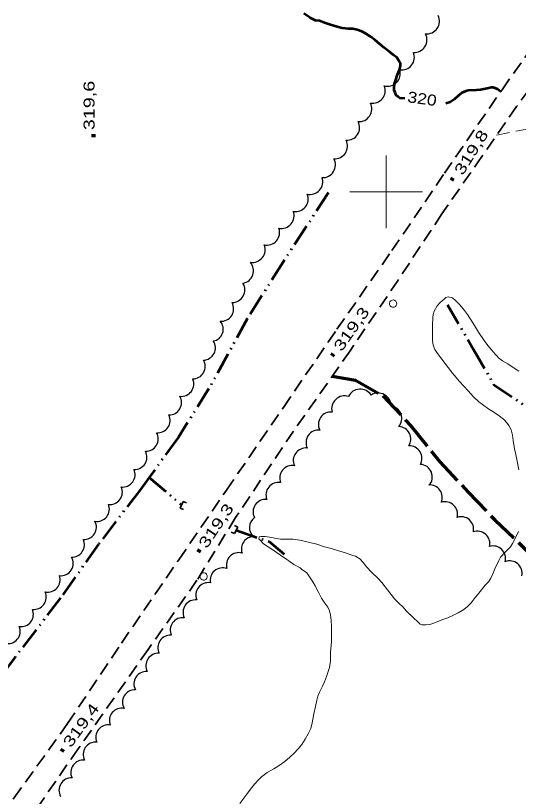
# Model space of a CAD drawing. Extents: x 240591 to 242335, y 5323482 to 5326937.
# Drawn here: x 241498.3 to 241636.3, y 5325234.2 to 5325448.3 of the extents above; entities that cross this region are included whole.
import ezdxf

# ---------------------------------------------------------------- set-up
doc = ezdxf.new("R2010")
doc.units = 0
doc.header["$LTSCALE"] = 1.2
for name, pattern in [('DASH_DOUBLE_DOT', [9.2, 5, -1.2, 0.3, -1.2, 0.3, -1.2]), ('LONG_DASHED', [7.5, 6, -1.5]), ('MEDIUM_DASHED', [4.5, 3, -1.5])]:
    doc.linetypes.add(name, pattern=pattern)
for name, color, linetype, lineweight in [('1', 7, 'Continuous', 53), ('19', 7, 'Continuous', 13), ('2', 7, 'Continuous', 13), ('21', 7, 'Continuous', 53), ('22', 7, 'LONG_DASHED', 70), ('26', 7, 'Continuous', 35), ('3', 7, 'Continuous', 140), ('36', 7, 'Continuous', 13), ('4', 7, 'DASH_DOUBLE_DOT', 53), ('44', 7, 'Continuous', 25), ('61', 7, 'Continuous', 13)]:
    doc.layers.add(name, color=color, linetype=linetype, lineweight=lineweight)

msp = doc.modelspace()

# ---------------------------------------------------------------- linework, layer by layer
at = {"layer": '1'}
for points in [[(241605.1, 5325425.6), (241603.8, 5325425.7), (241603.3, 5325426), (241602.8, 5325426.5), (241602.5, 5325427.2), (241602.2, 5325427.9), (241602.2, 5325428.5), (241602.3, 5325429.7), (241602.6, 5325430.4), (241603.1, 5325432.2), (241603.7, 5325433.4), (241603.9, 5325434.5), (241603.9, 5325435.3), (241603.6, 5325435.8), (241602.9, 5325436.8), (241601.9, 5325437.6), (241600.9, 5325438.4), (241599.4, 5325439.6), (241597, 5325441.6), (241595.8, 5325442.5), (241594.5, 5325443.3), (241593.3, 5325444), (241592.1, 5325444.4), (241590.9, 5325444.7), (241589.7, 5325444.7), (241587.9, 5325444.9), (241586.6, 5325445.2), (241584.7, 5325445.8), (241583.4, 5325446.2), (241581.7, 5325446.9), (241580.6, 5325447), (241579.5, 5325447.5), (241579.1, 5325447.8), (241577.4, 5325448.9)], [(241631.4, 5325427.5), (241630.6, 5325428.1), (241629.5, 5325428.6), (241628.8, 5325428.6), (241628.2, 5325428.4), (241625.9, 5325428), (241624.8, 5325427.9), (241622.5, 5325427.8), (241621.9, 5325427.6), (241620.8, 5325427.1), (241619.8, 5325426.3), (241618.7, 5325425.3), (241617.6, 5325424.6), (241616.4, 5325424.2)]]:
    msp.add_lwpolyline(points, dxfattribs=at)
at = {"layer": '19', "linetype": 'MEDIUM_DASHED'}
msp.add_lwpolyline([(241630.3, 5325415.5), (241640.5, 5325417.6), (241648.5, 5325417.1), (241657.7, 5325414.1), (241658.9, 5325416.3)], dxfattribs=at)
at = {"layer": '2'}
for points in [[(241636.4, 5325350.8), (241634.9, 5325351.8), (241633.4, 5325352.8), (241631.9, 5325353.7), (241630.8, 5325354.5), (241630.5, 5325354.9), (241629.9, 5325355.5), (241629, 5325356.6), (241627.9, 5325357.9), (241626.9, 5325359.2), (241625.3, 5325361.5), (241624.5, 5325362.9), (241623.8, 5325364.1), (241622.3, 5325366.4), (241621.5, 5325367.5), (241620.2, 5325369), (241619, 5325370.2), (241618.2, 5325370.9), (241617, 5325371.2), (241616.4, 5325371), (241615.9, 5325370.6), (241614.8, 5325369.7), (241614, 5325368.7), (241613.2, 5325367.3), (241612.9, 5325366.4), (241612.8, 5325365.5), (241612.7, 5325363.5), (241612.7, 5325361.7), (241612.7, 5325359.2), (241612.9, 5325358), (241613.4, 5325356.8), (241614.1, 5325355.7), (241615.3, 5325354.1), (241617, 5325351.8), (241618.2, 5325350.3), (241620.1, 5325348), (241621.3, 5325346.7), (241622.5, 5325345.4), (241624, 5325343.8), (241625.4, 5325342.4), (241626.4, 5325341.7), (241628.2, 5325340.4), (241629.3, 5325339.8), (241631, 5325338.6), (241632.2, 5325337.7), (241633.3, 5325336.5), (241633.7, 5325335.9), (241634.3, 5325334.7), (241634.7, 5325333.3), (241634.9, 5325331.8), (241635.2, 5325329.5), (241635.6, 5325328), (241635.9, 5325326.6), (241636.4, 5325323.8)], [(241636.3, 5325306.9), (241635.6, 5325305.3), (241634.7, 5325303.6), (241634.1, 5325302.7), (241633.4, 5325301.9), (241632.7, 5325301.2), (241631.4, 5325299.8), (241630.9, 5325298.9)]]:
    msp.add_lwpolyline(points, dxfattribs=at)
at = {"layer": '2', "linetype": 'LONG_DASHED'}
for points in [[(241630.9, 5325298.9), (241629.8, 5325296.6), (241629.3, 5325295.3), (241628.7, 5325294.1), (241628.1, 5325293.1), (241627.2, 5325292.2), (241625.4, 5325290), (241624.2, 5325288.4), (241623.3, 5325287.3), (241622.3, 5325286.3), (241621.3, 5325285.5), (241619.8, 5325284.6), (241618.3, 5325283.8), (241616.9, 5325283.2), (241615.6, 5325282.7), (241613.1, 5325281.7), (241612, 5325281.4), (241610.9, 5325281.3), (241609.8, 5325281.3), (241609.3, 5325281.5), (241608.8, 5325282), (241607.4, 5325283.3), (241605.6, 5325285), (241604.6, 5325286.2), (241603.6, 5325287.1), (241602.3, 5325288.4), (241601.4, 5325289.6), (241600.4, 5325290.9), (241598.8, 5325292.9), (241597.7, 5325294.1), (241596.1, 5325295.6), (241594.6, 5325297.2), (241593.7, 5325298.4), (241592.8, 5325299.4), (241591.6, 5325300.1), (241590.9, 5325300.3), (241588.6, 5325301.1), (241586.9, 5325301.6), (241584.9, 5325302.2), (241583.1, 5325302.7), (241581, 5325303.4), (241579.1, 5325303.9), (241576.3, 5325304.5), (241574.5, 5325304.8), (241573.1, 5325304.8), (241571, 5325304.8), (241569.4, 5325305), (241568.6, 5325305.2), (241566.8, 5325305.5), (241565.7, 5325305.5), (241565.2, 5325305.4), (241565.1, 5325304.9), (241565.5, 5325304.4), (241566.3, 5325303.6), (241566.9, 5325303.1), (241568.4, 5325302.2), (241569.8, 5325301.2), (241571, 5325300.4), (241572.8, 5325299.2), (241573.3, 5325298.8), (241574.7, 5325297.8), (241576.4, 5325296.9), (241576.8, 5325296.5), (241578.2, 5325295.5), (241578.6, 5325295), (241579.9, 5325293.1), (241580.5, 5325292), (241581.5, 5325290.1), (241582.3, 5325288.6), (241583.2, 5325287.2), (241584, 5325286.1), (241584.5, 5325285.1), (241584.7, 5325283.9), (241584.9, 5325282.6), (241585, 5325280.7), (241585, 5325279.6), (241585, 5325276.8), (241584.9, 5325275.6), (241584.7, 5325273.9), (241584.7, 5325272.7), (241584.7, 5325271.3)], [(241584.7, 5325271.3), (241584.5, 5325269.6), (241584.3, 5325269), (241583.6, 5325267.1), (241583.1, 5325265.7), (241582.5, 5325264.5), (241581.7, 5325262.8), (241581.3, 5325261.7), (241581, 5325260.6), (241580.6, 5325258.9), (241580.2, 5325256.9), (241579.7, 5325254.4), (241579.3, 5325252.9), (241578.6, 5325251.4), (241577.8, 5325249.9), (241576.9, 5325248.5), (241575.9, 5325247.3), (241574.8, 5325246.1), (241573.6, 5325245), (241572.2, 5325243.8), (241570.7, 5325242.7), (241569.2, 5325241.8), (241567.4, 5325240.8), (241565.8, 5325239.6), (241565.1, 5325238.9), (241563.9, 5325237.6), (241562.8, 5325236.2), (241561.8, 5325234.9), (241559.9, 5325232.3)]]:
    msp.add_lwpolyline(points, dxfattribs=at)
at = {"layer": '21', "linetype": 'MEDIUM_DASHED', "lineweight": 35}
for points in [[(241366.3, 5325064.2), (241373.2, 5325063), (241379.4, 5325064.5), (241383, 5325067), (241395.1, 5325084.2), (241406.9, 5325101.7), (241421.3, 5325123.9), (241435, 5325143.3), (241450.8, 5325165.7), (241464.8, 5325185.7), (241482.4, 5325211.2), (241497.9, 5325233.8), (241512.6, 5325254.2), (241527.4, 5325276.3), (241543.1, 5325299.1), (241556.2, 5325318.2), (241571.8, 5325340.9), (241586.5, 5325362.3), (241601.6, 5325383.9), (241616, 5325405.1), (241631.8, 5325428), (241643, 5325443.8)], [(241648.8, 5325441.1), (241635.8, 5325423.4), (241626.3, 5325409.7), (241615.3, 5325394), (241603.3, 5325375.8), (241590.1, 5325356.4), (241574.6, 5325334.4), (241558.7, 5325310.7), (241548.1, 5325293.5), (241534.7, 5325274.5), (241515.5, 5325247.3), (241501.4, 5325226.9), (241486.9, 5325205.4), (241470.6, 5325181.9), (241454.1, 5325158.1), (241439.1, 5325136.5), (241424.2, 5325115.1), (241409.8, 5325096.8), (241395.9, 5325076.6), (241386.9, 5325063.3), (241384.2, 5325058.9), (241384.2, 5325055.3)]]:
    msp.add_lwpolyline(points, dxfattribs=at)
at = {"layer": '22'}
msp.add_lwpolyline([(241585.2, 5325349.5), (241591.6, 5325348.4), (241599.1, 5325344.1), (241606.7, 5325335.9), (241614.6, 5325326.1), (241622.5, 5325317.7), (241629.8, 5325310.1), (241636.3, 5325303.9), (241643, 5325297.1), (241652.2, 5325290.3), (241658.3, 5325286.1), (241663.5, 5325280.6), (241669.4, 5325275.7), (241675.5, 5325271.4), (241680.7, 5325270.7), (241686.8, 5325276.1), (241692.1, 5325282.4), (241699.9, 5325288.3), (241706.5, 5325293.8), (241712.3, 5325300.5), (241720.6, 5325307.4), (241725.4, 5325314), (241731.4, 5325322), (241734.5, 5325325.9)], dxfattribs=at)
at = {"layer": '26'}
for p, q in [((241543.5, 5325313.3), (241544.3, 5325315.1)), ((241544.3, 5325315.1), (241545.2, 5325314.7)), ((241543.5, 5325313.3), (241544.4, 5325312.9)), ((241559.3, 5325308.1), (241558.4, 5325308.5)), ((241559.3, 5325308.1), (241558.4, 5325306.3)), ((241558.4, 5325306.3), (241557.5, 5325306.7))]:
    msp.add_line(p, q, dxfattribs=at)
at = {"layer": '3'}
for p, q in [((241519.7, 5325415), (241519.7, 5325415.8)), ((241617.9, 5325403.1), (241618.3, 5325403.8)), ((241585.1, 5325355), (241585.6, 5325355.6)), ((241548.4, 5325301.2), (241548.9, 5325301.9)), ((241510.9, 5325246.6), (241511.4, 5325247.2))]:
    msp.add_line(p, q, dxfattribs=at)
at = {"layer": '36'}
for centre in [(241601.913, 5325369.36), (241549.923, 5325294.54)]:
    msp.add_ellipse(centre, major_axis=(0.261, -0.965), ratio=0.99964, dxfattribs=at)
at = {"layer": '4'}
msp.add_line((241535, 5325321.7), (241543.9, 5325314.2), dxfattribs=at)
for points in [[(241584.2, 5325399.8), (241571.8, 5325380.9), (241561.9, 5325365.2), (241551.4, 5325346.1), (241543, 5325332.7), (241535, 5325321.7)], [(241616.8, 5325369), (241624, 5325356.8), (241629.5, 5325347.2), (241643.1, 5325338)], [(241535, 5325321.7), (241532.6, 5325318.4), (241521.1, 5325303.4), (241510.7, 5325288.7), (241498.2, 5325272.4), (241485.9, 5325256.1), (241475.2, 5325240.2), (241463.5, 5325224.4), (241453.7, 5325207.4), (241442.8, 5325192.3), (241432.8, 5325176), (241421.8, 5325159.9), (241410.9, 5325144.8), (241399.3, 5325129.2), (241388.8, 5325116.7), (241384.7, 5325110.5)], [(241558.9, 5325307.2), (241567.9, 5325304.1), (241572, 5325300.7)]]:
    msp.add_lwpolyline(points, dxfattribs=at)
at = {"layer": '44'}
for centre, radius, start, end in [((241592.598, 5325422.721), 3.472, 265.41494, 27.41422), ((241549.769, 5325357.229), 3.39, 271.70344, 33.69742), ((241543.846, 5325347.315), 3.394, 262.45097, 24.27285), ((241537.357, 5325337.328), 3.393, 264.46711, 26.27701), ((241584.844, 5325336.201), 3.434, 84.71736, 206.47217), ((241603.367, 5325332.226), 3.417, 326.30219, 87.94459), ((241534.082, 5325332.264), 3.396, 268.10704, 29.76662), ((241581.436, 5325331.263), 3.423, 84.39588, 206.41954), ((241531, 5325327.262), 3.377, 266.77785, 28.42878), ((241527.738, 5325322.455), 3.391, 262.9141, 25.04535), ((241524.241, 5325317.671), 3.39, 262.52593, 24.73809), ((241559.575, 5325297.686), 3.401, 74.92253, 196.84866), ((241551.216, 5325289.423), 3.433, 80.70797, 202.30093), ((241527.477, 5325255.036), 3.415, 79.14544, 201.04681)]:
    msp.add_arc(centre, radius, start, end, dxfattribs=at)
for centre, major_axis, ratio, start_param, end_param in [((241611.148, 5325446.779), (2.849, -1.993), 0.999951, 5.2224799, 7.3496325), ((241607.727, 5325441.684), (2.923, -1.894), 0.999461, 5.2190396, 7.3474591), ((241604.275, 5325436.883), (2.726, -2.162), 0.999805, 5.2196706, 7.3451534), ((241600.382, 5325432.426), (2.505, -2.418), 0.999951, 5.2208919, 7.349463), ((241596.268, 5325427.749), (-1.286, 3.232), 0.999984, 2.5930332, 4.7202271), ((241589.25, 5325417.622), (-1.606, 3.087), 0.999984, 2.5959884, 4.7227987), ((241585.926, 5325412.552), (0.188, 3.477), 0.999995, 3.118947, 5.2431425), ((241582.595, 5325407.387), (2.977, -1.844), 0.999807, 5.2198642, 7.3426411), ((241579.139, 5325402.763), (2.349, -2.567), 0.999605, 5.3190476, 7.4430044), ((241575.141, 5325398.075), (2.7, -2.195), 0.999978, 5.2185393, 7.3470971), ((241571.278, 5325393.433), (2.642, -2.253), 0.999913, 5.2190753, 7.3474428), ((241567.3, 5325388.881), (2.596, -2.324), 0.999978, 5.2224875, 7.3494721), ((241563.308, 5325384.129), (2.448, -2.507), 0.999771, 5.3497295, 7.4766396), ((241560.14, 5325378.357), (-0.671, 3.422), 0.999995, 3.117985, 5.2440886), ((241557.769, 5325373.11), (3.021, -1.71), 0.99956, 5.2188214, 7.3469867), ((241554.693, 5325367.969), (2.936, -1.86), 0.999735, 5.2185351, 7.3497879), ((241552.048, 5325362.331), (-2.153, 2.457), 0.999982, 2.5889097, 4.7190857), ((241546.976, 5325352.091), (-1.721, 2.911), 0.999983, 2.5970277, 4.7221857), ((241588.608, 5325340.505), (-2.448, 2.584), 0.999979, 5.2189198, 7.3469599), ((241592.881, 5325342.369), (-1.553, -3.19), 0.999985, 2.5926148, 4.7191259), ((241597.785, 5325341.214), (-3.614, -0.099), 0.999995, 3.1186726, 5.2434248), ((241540.481, 5325342.222), (2.446, -2.351), 0.999926, 5.4543049, 7.5834552), ((241600.888, 5325337.853), (3.199, 1.216), 0.997533, 5.2143954, 7.3413938), ((241577.945, 5325326.346), (-2.768, 2.01), 0.999994, 5.2159583, 7.3444904), ((241606.412, 5325326.907), (-3.051, 1.565), 0.999995, 3.1146527, 5.2452189), ((241574.232, 5325321.535), (-1.809, 2.913), 0.999961, 5.5490564, 7.6728778), ((241609.279, 5325321.869), (2.052, 2.704), 0.999604, 4.6085165, 6.8908495), ((241570.443, 5325316.913), (-2.653, 2.157), 0.999978, 5.219688, 7.3475095), ((241612.016, 5325316.232), (-2.126, 2.648), 0.999984, 3.6327376, 5.6854306), ((241520.673, 5325313.004), (-1.277, 3.139), 0.999983, 2.5913572, 4.7217323), ((241566.899, 5325312.255), (-1.351, -3.126), 0.999852, 3.4404952, 5.5946511), ((241616.144, 5325311.614), (2.373, 2.49), 0.998912, 5.2192108, 7.341429), ((241565.882, 5325307.969), (0.489, -3.357), 0.999938, 3.6318547, 5.4218673), ((241620.591, 5325307.517), (2.28, 2.552), 0.999799, 5.2211816, 7.346027), ((241517.116, 5325308.077), (2.846, -1.855), 0.999637, 5.2175067, 7.3459954), ((241563.671, 5325302.071), (-0.314, -3.38), 0.99976, 3.2250904, 5.1354995), ((241625.034, 5325303.528), (2.293, 2.545), 0.999861, 5.2165704, 7.3446874), ((241513.848, 5325303.206), (2.309, 2.452), 0.996125, 3.8459608, 5.9229377), ((241629.369, 5325299.474), (2.365, 2.481), 0.998745, 5.2149481, 7.3410726), ((241510.794, 5325298.112), (1.949, 2.75), 0.996399, 3.6364266, 5.8744482), ((241633.896, 5325295.407), (2.453, 2.38), 0.999591, 5.3192169, 7.4477797), ((241555.129, 5325293.487), (-2.231, 2.601), 0.999911, 5.2191745, 7.3440431), ((241507.181, 5325293.641), (2.54, -2.249), 0.999858, 5.2168705, 7.3473823), ((241503.358, 5325288.896), (-1.406, 3.095), 0.999983, 2.597608, 4.7215363), ((241547.702, 5325284.71), (-2.811, 1.962), 0.999799, 5.2227698, 7.3454562), ((241499.845, 5325284.189), (2.674, -2.081), 0.999994, 5.2211856, 7.3483541), ((241544.163, 5325279.835), (-2.541, 2.27), 0.999488, 5.306536, 7.4375917), ((241496.25, 5325279.485), (1.911, 2.773), 0.996619, 3.4999184, 5.728722), ((241540.792, 5325275.024), (-2.44, 2.391), 0.999882, 5.409151, 7.5307292), ((241537.487, 5325270.067), (-2.846, 1.884), 0.99991, 5.2200727, 7.3483479), ((241534.226, 5325265.086), (-2.671, 2.124), 0.99959, 5.3152991, 7.4419915), ((241531.074, 5325260.086), (-2.915, 1.763), 0.999994, 5.2164076, 7.3481609), ((241523.735, 5325250.446), (-2.103, 2.684), 0.999927, 5.4551627, 7.585792), ((241520.3, 5325245.733), (-2.714, 2.068), 0.998813, 5.2777933, 7.4046581), ((241516.906, 5325240.79), (-2.799, 1.967), 0.999191, 5.220965, 7.3406403), ((241513.66, 5325235.912), (-2.899, 1.8), 0.999949, 5.2209597, 7.3475429)]:
    msp.add_ellipse(centre, major_axis=major_axis, ratio=ratio, start_param=start_param, end_param=end_param, dxfattribs=at)
at = {"layer": '61'}
for points in [[(241600, 5325410), (241600, 5325400), (241600, 5325390)], [(241590, 5325400), (241600, 5325400), (241610, 5325400)]]:
    msp.add_lwpolyline(points, dxfattribs=at)

# ---------------------------------------------------------------- texts
at = {"layer": '1', "width": 1.2}
msp.add_text('320', height=3, rotation=352.091, dxfattribs=at).set_placement((241605.7, 5325424.6))
at = {"layer": '3', "width": 1.35}
for s, height, rotation, p in [('319,6', 3, 90, (241520, 5325416.9)), ('319,8', 2.999, 57.882, (241621, 5325404.3)), ('319,3', 2.999, 54.779, (241587.8, 5325356)), ('319,3', 3, 56.1, (241550.8, 5325302)), ('319,4', 3, 53.835, (241513.5, 5325247.4))]:
    msp.add_text(s, height=height, rotation=rotation, dxfattribs=at).set_placement(p)

doc.saveas('drawing.dxf')
